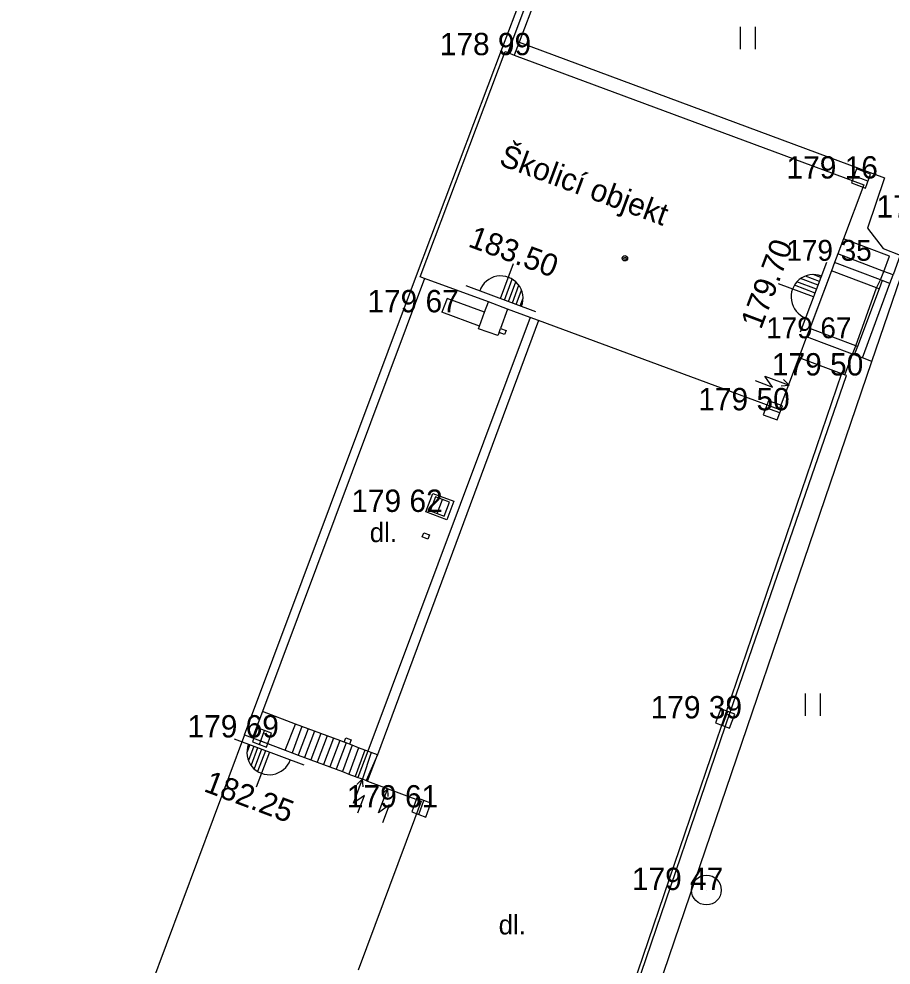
# Model space of a CAD drawing. Extents: x -537755 to -537431, y -1180722 to -1180510.
# Drawn here: x -537534.25 to -537504.97, y -1180583.92 to -1180552.16 of the extents above; entities that cross this region are included whole.
import ezdxf

# ---------------------------------------------------------------- set-up
doc = ezdxf.new("R2010")
doc.units = 0
for name, color, linetype in [('Vrstva 1', 7, 'Continuous'), ('Vrstva 11', 7, 'Continuous'), ('Vrstva 24', 7, 'Continuous'), ('Vrstva 27', 7, 'Continuous'), ('Vrstva 3', 7, 'Continuous'), ('Vrstva 36', 7, 'Continuous'), ('Vrstva 37', 7, 'Continuous'), ('Vrstva 39', 7, 'Continuous'), ('Vrstva 40', 7, 'Continuous'), ('Vrstva 41', 7, 'Continuous'), ('Vrstva 5', 7, 'Continuous'), ('Vrstva 6', 7, 'Continuous'), ('Vrstva 7', 7, 'Continuous')]:
    doc.layers.add(name, color=color, linetype=linetype)

msp = doc.modelspace()

# ---------------------------------------------------------------- linework, layer by layer
at = {"layer": 'Vrstva 1'}
for p, q in [((-537518.01, -1180553.12), (-537518.01, -1180553.12)), ((-537517.92, -1180553.26), (-537517.92, -1180553.26)), ((-537517.62, -1180553.38), (-537517.62, -1180553.38)), ((-537505.98, -1180557.52), (-537505.98, -1180557.52)), ((-537505.19, -1180557.5), (-537505.19, -1180557.5)), ((-537505.88, -1180557.73), (-537505.88, -1180557.73)), ((-537505.76, -1180559.19), (-537505.76, -1180559.19)), ((-537505.24, -1180559.87), (-537505.24, -1180559.87)), ((-537506.15, -1180560.28), (-537506.15, -1180560.28)), ((-537505.02, -1180560.13), (-537505.02, -1180560.13)), ((-537507.05, -1180560.83), (-537507.05, -1180560.83)), ((-537505.46, -1180561.19), (-537505.46, -1180561.19)), ((-537505.03, -1180561.09), (-537505.03, -1180561.09)), ((-537520.05, -1180562.01), (-537520.05, -1180562.01)), ((-537518.82, -1180562.56), (-537518.82, -1180562.56)), ((-537517.89, -1180562.62), (-537517.89, -1180562.62)), ((-537507.62, -1180562.34), (-537507.62, -1180562.34)), ((-537518.17, -1180562.79), (-537518.17, -1180562.79)), ((-537517.35, -1180562.88), (-537517.35, -1180562.88)), ((-537516.97, -1180562.72), (-537516.97, -1180562.72)), ((-537506.83, -1180562.88), (-537506.83, -1180562.88)), ((-537505.93, -1180563.54), (-537505.93, -1180563.54)), ((-537506.47, -1180564.13), (-537506.47, -1180564.13)), ((-537506.18, -1180564.21), (-537506.18, -1180564.21)), ((-537508.39, -1180564.46), (-537508.39, -1180564.46)), ((-537508.94, -1180565.3), (-537508.94, -1180565.3)), ((-537508.73, -1180565.27), (-537508.73, -1180565.27)), ((-537506.54, -1180566.1), (-537506.54, -1180566.1)), ((-537519.65, -1180568.35), (-537519.65, -1180568.35)), ((-537520.59, -1180568.71), (-537520.59, -1180568.71)), ((-537520.47, -1180569.48), (-537520.47, -1180569.48)), ((-537510.54, -1180575.64), (-537510.54, -1180575.64)), ((-537524.96, -1180575.83), (-537524.96, -1180575.83)), ((-537526.09, -1180576.28), (-537526.09, -1180576.28)), ((-537526.2, -1180576.37), (-537526.2, -1180576.37)), ((-537523.09, -1180576.36), (-537523.09, -1180576.36)), ((-537522.38, -1180576.32), (-537522.38, -1180576.32)), ((-537525.31, -1180576.71), (-537525.31, -1180576.71)), ((-537522.21, -1180576.86), (-537522.21, -1180576.86)), ((-537522.71, -1180577.67), (-537522.71, -1180577.67)), ((-537521.87, -1180577.99), (-537521.87, -1180577.99)), ((-537520.75, -1180578.42), (-537520.75, -1180578.42)), ((-537520.74, -1180578.63), (-537520.74, -1180578.63)), ((-537520.97, -1180579.02), (-537520.97, -1180579.02)), ((-537511.17, -1180581.4), (-537511.17, -1180581.4)), ((-537522.02, -1180581.84), (-537522.02, -1180581.84))]:
    msp.add_line(p, q, dxfattribs=at)
at = {"layer": 'Vrstva 11'}
for p, q in [((-537517.457, -1180552.946), (-537505.19, -1180557.5)), ((-537519.877, -1180561.541), (-537520.05, -1180562.01)), ((-537518.616, -1180562.007), (-537519.877, -1180561.541)), ((-537517.842, -1180561.902), (-537518.077, -1180562.55)), ((-537517.088, -1180562.181), (-537522.537, -1180576.738)), ((-537518.789, -1180562.476), (-537520.05, -1180562.01)), ((-537506.635, -1180564.068), (-537510.498, -1180575.39)), ((-537510.376, -1180575.435), (-537506.47, -1180564.13)), ((-537506.47, -1180564.13), (-537506.524, -1180564.11)), ((-537524.96, -1180575.83), (-537526.076, -1180575.412)), ((-537510.498, -1180575.39), (-537515.67, -1180590.55)), ((-537515.547, -1180590.592), (-537510.376, -1180575.435)), ((-537525.31, -1180576.71), (-537524.96, -1180575.83)), ((-537524.75, -1180575.909), (-537525.081, -1180576.791)), ((-537524.538, -1180575.988), (-537524.87, -1180576.87)), ((-537524.326, -1180576.067), (-537524.658, -1180576.95)), ((-537524.115, -1180576.147), (-537524.447, -1180577.029)), ((-537523.903, -1180576.226), (-537524.235, -1180577.109)), ((-537523.334, -1180576.439), (-537523.277, -1180576.29)), ((-537523.277, -1180576.29), (-537523.09, -1180576.36)), ((-537523.691, -1180576.305), (-537524.024, -1180577.189)), ((-537523.48, -1180576.384), (-537523.812, -1180577.268)), ((-537523.268, -1180576.464), (-537523.601, -1180577.348)), ((-537523.057, -1180576.543), (-537523.389, -1180577.427)), ((-537523.09, -1180576.36), (-537523.147, -1180576.509)), ((-537522.845, -1180576.622), (-537523.178, -1180577.507)), ((-537522.633, -1180576.701), (-537522.966, -1180577.586)), ((-537522.537, -1180576.738), (-537522.868, -1180577.623)), ((-537522.422, -1180576.781), (-537522.71, -1180577.67))]:
    msp.add_line(p, q, dxfattribs=at)
for points in [[(-537505.19, -1180557.5), (-537505.76, -1180559.19), (-537505.24, -1180559.87), (-537504.66, -1180560.09), (-537504.902, -1180560.752)], [(-537505.93, -1180563.54), (-537505.011, -1180561.039), (-537504.902, -1180560.752), (-537505.211, -1180560.635), (-537506.757, -1180560.051)], [(-537505.011, -1180561.039), (-537505.265, -1180560.943), (-537505.319, -1180560.922), (-537506.866, -1180560.338)], [(-537505.371, -1180561.223), (-537505.46, -1180561.19), (-537506.972, -1180560.619)], [(-537505.265, -1180560.943), (-537505.371, -1180561.223), (-537506.102, -1180563.155), (-537506.208, -1180563.436)], [(-537518.13, -1180562.69), (-537518.17, -1180562.79), (-537518.82, -1180562.56), (-537518.789, -1180562.476), (-537518.616, -1180562.007), (-537518.488, -1180561.663)], [(-537506.102, -1180563.155), (-537506.156, -1180563.135), (-537507.702, -1180562.55)], [(-537505.614, -1180563.66), (-537505.93, -1180563.54), (-537506.208, -1180563.436), (-537506.262, -1180563.416), (-537507.808, -1180562.831)], [(-537520.356, -1180568.086), (-537519.65, -1180568.35), (-537519.884, -1180568.974), (-537520.59, -1180568.71), (-537520.356, -1180568.086)], [(-537522.543, -1180577.746), (-537522.21, -1180576.86), (-537522.422, -1180576.781), (-537522.537, -1180576.738), (-537522.633, -1180576.701), (-537522.845, -1180576.622), (-537523.057, -1180576.543), (-537523.147, -1180576.509), (-537523.268, -1180576.464), (-537523.334, -1180576.439), (-537523.48, -1180576.384), (-537523.691, -1180576.305), (-537523.903, -1180576.226), (-537524.115, -1180576.147), (-537524.326, -1180576.067), (-537524.538, -1180575.988), (-537524.75, -1180575.909), (-537524.96, -1180575.83)]]:
    msp.add_lwpolyline(points, dxfattribs=at)
at = {"layer": 'Vrstva 24'}
for p, q in [((-537508.945, -1180564.518), (-537509.209, -1180564.151)), ((-537509.209, -1180564.151), (-537508.39, -1180564.46)), ((-537509.532, -1180564.296), (-537508.945, -1180564.518)), ((-537508.658, -1180564.475), (-537508.39, -1180564.46)), ((-537508.39, -1180564.46), (-537508.58, -1180564.27)), ((-537523.018, -1180578.489), (-537522.71, -1180577.67)), ((-537522.71, -1180577.67), (-537522.9, -1180577.86)), ((-537522.694, -1180577.938), (-537522.71, -1180577.67)), ((-537522.178, -1180578.809), (-537521.87, -1180577.99)), ((-537521.87, -1180577.99), (-537522.06, -1180578.18)), ((-537521.854, -1180578.258), (-537521.87, -1180577.99)), ((-537522.652, -1180578.225), (-537523.018, -1180578.489)), ((-537522.872, -1180578.812), (-537522.652, -1180578.225)), ((-537521.812, -1180578.545), (-537522.178, -1180578.809)), ((-537522.032, -1180579.132), (-537521.812, -1180578.545))]:
    msp.add_line(p, q, dxfattribs=at)
at = {"layer": 'Vrstva 27'}
for p, q in [((-537505.746, -1180557.607), (-537506.214, -1180557.433)), ((-537508.706, -1180565.387), (-537509.174, -1180565.213)), ((-537520.207, -1180568.764), (-537520.033, -1180568.296)), ((-537510.627, -1180575.874), (-537510.453, -1180575.406)), ((-537526.177, -1180576.514), (-537526.003, -1180576.046)), ((-537520.827, -1180578.864), (-537520.653, -1180578.396))]:
    msp.add_line(p, q, dxfattribs=at)
for points in [[(-537505.658, -1180557.373), (-537506.127, -1180557.198), (-537506.302, -1180557.667), (-537505.833, -1180557.842)], [(-537508.618, -1180565.153), (-537509.087, -1180564.978), (-537509.262, -1180565.447), (-537508.793, -1180565.622)], [(-537519.973, -1180568.852), (-537519.798, -1180568.383), (-537520.267, -1180568.208), (-537520.442, -1180568.677)], [(-537510.393, -1180575.962), (-537510.218, -1180575.493), (-537510.687, -1180575.318), (-537510.862, -1180575.787)], [(-537525.943, -1180576.602), (-537525.768, -1180576.133), (-537526.237, -1180575.958), (-537526.412, -1180576.427)], [(-537520.593, -1180578.952), (-537520.418, -1180578.483), (-537520.887, -1180578.308), (-537521.062, -1180578.777)]]:
    msp.add_lwpolyline(points, close=True, dxfattribs=at)
msp.add_circle((-537511.17, -1180581.4), 0.5, dxfattribs=at)
at = {"layer": 'Vrstva 36'}
for p, q in [((-537510.022, -1180553.183), (-537510.022, -1180552.433)), ((-537509.522, -1180553.183), (-537509.522, -1180552.433)), ((-537507.84, -1180575.551), (-537507.84, -1180574.801)), ((-537507.34, -1180575.551), (-537507.34, -1180574.801))]:
    msp.add_line(p, q, dxfattribs=at)
at = {"layer": 'Vrstva 37'}
for p, q in [((-537518.078, -1180561.548), (-537517.64, -1180560.369)), ((-537508.012, -1180562.665), (-537507.128, -1180560.327)), ((-537517.947, -1180561.597), (-537517.687, -1180560.898)), ((-537517.816, -1180561.646), (-537517.57, -1180560.986)), ((-537507.471, -1180561.234), (-537508.129, -1180560.985)), ((-537507.421, -1180561.103), (-537508.011, -1180560.88)), ((-537507.372, -1180560.972), (-537507.846, -1180560.793)), ((-537507.322, -1180560.841), (-537507.582, -1180560.743)), ((-537519.25, -1180561.113), (-537516.906, -1180561.983)), ((-537517.684, -1180561.694), (-537517.465, -1180561.104)), ((-537517.553, -1180561.743), (-537517.376, -1180561.268)), ((-537507.57, -1180561.496), (-537508.747, -1180561.051)), ((-537507.52, -1180561.365), (-537508.217, -1180561.102)), ((-537517.422, -1180561.792), (-537517.325, -1180561.531)), ((-537524.672, -1180577.213), (-537527.012, -1180576.331)), ((-537526.497, -1180576.525), (-537526.595, -1180576.785)), ((-537526.366, -1180576.575), (-537526.545, -1180577.049)), ((-537526.235, -1180576.624), (-537526.457, -1180577.214)), ((-537526.104, -1180576.673), (-537526.352, -1180577.332)), ((-537525.842, -1180576.772), (-537526.285, -1180577.949)), ((-537525.973, -1180576.723), (-537526.236, -1180577.42))]:
    msp.add_line(p, q, dxfattribs=at)
for centre, start, end in [((-537518.075, -1180561.54), 338.9961, 160.2421), ((-537507.578, -1180561.493), 68.663, 249.909), ((-537525.845, -1180576.78), 158.7366, 339.9827)]:
    msp.add_arc(centre, 0.75, start, end, dxfattribs=at)
at = {"layer": 'Vrstva 39'}
for radius in [0.09, 0.0398]:
    msp.add_circle((-537513.906, -1180560.195), radius, dxfattribs=at)
at = {"layer": 'Vrstva 5'}
for p, q in [((-537520.777, -1180560.817), (-537517.92, -1180553.26)), ((-537517.92, -1180553.26), (-537517.835, -1180553.292)), ((-537517.835, -1180553.292), (-537517.62, -1180553.38)), ((-537517.62, -1180553.38), (-537505.88, -1180557.73)), ((-537505.88, -1180557.73), (-537506.566, -1180559.546)), ((-537506.566, -1180559.546), (-537506.757, -1180560.051)), ((-537505.02, -1180560.13), (-537506.566, -1180559.546)), ((-537506.757, -1180560.051), (-537506.866, -1180560.338)), ((-537506.866, -1180560.338), (-537506.972, -1180560.619)), ((-537505.211, -1180560.635), (-537505.02, -1180560.13)), ((-537506.972, -1180560.619), (-537507.702, -1180562.55)), ((-537505.319, -1180560.922), (-537505.211, -1180560.635)), ((-537520.634, -1180560.87), (-537520.777, -1180560.817)), ((-537518.488, -1180561.663), (-537520.634, -1180560.87)), ((-537505.46, -1180561.19), (-537505.319, -1180560.922)), ((-537506.156, -1180563.135), (-537505.46, -1180561.19)), ((-537517.088, -1180562.181), (-537517.842, -1180561.902)), ((-537516.807, -1180562.285), (-537522.21, -1180576.86)), ((-537516.807, -1180562.285), (-537517.088, -1180562.181)), ((-537508.73, -1180565.27), (-537516.807, -1180562.285)), ((-537518.13, -1180562.69), (-537518.077, -1180562.55)), ((-537518.077, -1180562.55), (-537517.89, -1180562.62)), ((-537517.89, -1180562.62), (-537517.943, -1180562.76)), ((-537507.702, -1180562.55), (-537507.808, -1180562.831)), ((-537517.943, -1180562.76), (-537518.13, -1180562.69)), ((-537507.808, -1180562.831), (-537508.07, -1180563.525)), ((-537506.262, -1180563.416), (-537506.156, -1180563.135)), ((-537508.07, -1180563.525), (-537508.73, -1180565.27)), ((-537508.07, -1180563.525), (-537506.635, -1180564.068)), ((-537506.524, -1180564.11), (-537506.262, -1180563.416)), ((-537506.635, -1180564.068), (-537506.524, -1180564.11)), ((-537520.71, -1180569.55), (-537520.657, -1180569.41)), ((-537520.523, -1180569.62), (-537520.71, -1180569.55)), ((-537520.657, -1180569.41), (-537520.47, -1180569.48)), ((-537520.47, -1180569.48), (-537520.523, -1180569.62)), ((-537526.673, -1180576.192), (-537534.25, -1180596.49)), ((-537526.673, -1180576.192), (-537526.406, -1180576.293)), ((-537526.406, -1180576.293), (-537525.31, -1180576.71)), ((-537525.31, -1180576.71), (-537525.081, -1180576.791)), ((-537525.081, -1180576.791), (-537524.87, -1180576.87)), ((-537524.87, -1180576.87), (-537524.658, -1180576.95)), ((-537522.21, -1180576.86), (-537522.587, -1180577.729)), ((-537524.658, -1180576.95), (-537524.447, -1180577.029)), ((-537524.447, -1180577.029), (-537524.235, -1180577.109)), ((-537524.235, -1180577.109), (-537524.024, -1180577.189)), ((-537524.024, -1180577.189), (-537523.812, -1180577.268)), ((-537523.812, -1180577.268), (-537523.601, -1180577.348)), ((-537523.601, -1180577.348), (-537523.389, -1180577.427)), ((-537523.389, -1180577.427), (-537523.178, -1180577.507)), ((-537523.178, -1180577.507), (-537522.966, -1180577.586)), ((-537522.966, -1180577.586), (-537522.868, -1180577.623)), ((-537522.868, -1180577.623), (-537522.71, -1180577.67)), ((-537522.71, -1180577.67), (-537522.587, -1180577.729)), ((-537522.587, -1180577.729), (-537522.543, -1180577.746)), ((-537522.543, -1180577.746), (-537520.75, -1180578.42)), ((-537520.75, -1180578.42), (-537520.97, -1180579.02)), ((-537521.813, -1180581.267), (-537522.02, -1180581.84))]:
    msp.add_line(p, q, dxfattribs=at)
at = {"layer": 'Vrstva 6'}
for p, q in [((-537507.05, -1180560.83), (-537507.62, -1180562.34)), ((-537517.842, -1180561.902), (-537518.488, -1180561.663)), ((-537526.2, -1180576.37), (-537525.31, -1180576.71)), ((-537520.97, -1180579.02), (-537521.813, -1180581.267)), ((-537522.02, -1180581.84), (-537522.865, -1180584.086))]:
    msp.add_line(p, q, dxfattribs=at)
at = {"layer": 'Vrstva 7'}
for p, q in [((-537518.01, -1180553.12), (-537515.69, -1180546.957)), ((-537515.381, -1180546.773), (-537517.835, -1180553.292)), ((-537515.2, -1180546.95), (-537517.457, -1180552.946)), ((-537505.614, -1180563.66), (-537501.7, -1180552.176)), ((-537517.457, -1180552.946), (-537517.62, -1180553.38)), ((-537520.902, -1180560.771), (-537518.01, -1180553.12)), ((-537526.673, -1180576.192), (-537520.902, -1180560.771)), ((-537520.634, -1180560.87), (-537526.076, -1180575.412)), ((-537514.8, -1180590.62), (-537505.614, -1180563.66)), ((-537526.076, -1180575.412), (-537526.406, -1180576.293))]:
    msp.add_line(p, q, dxfattribs=at)

# ---------------------------------------------------------------- texts
at = {"layer": 'Vrstva 3'}
for s, height, p in [('178 99 ', 0.75, (-537520.12, -1180553.38)), ('179 16 ', 0.75, (-537508.48, -1180557.52)), ('179 31 ', 0.75, (-537505.46, -1180558.83)), ('179 35 ', 0.7, (-537508.483, -1180560.28)), ('179 67 ', 0.75, (-537522.55, -1180562.01)), ('179 67 ', 0.7, (-537509.163, -1180562.88)), ('179 50 ', 0.75, (-537508.97, -1180564.13)), ('179 50 ', 0.75, (-537511.44, -1180565.3)), ('179 62 ', 0.75, (-537523.09, -1180568.71)), ('179 39 ', 0.75, (-537513.04, -1180575.64)), ('179 69 ', 0.75, (-537528.59, -1180576.28)), ('179 61 ', 0.75, (-537523.24, -1180578.63)), ('179 47 ', 0.75, (-537513.67, -1180581.4))]:
    msp.add_text(s, height=height, dxfattribs=at).set_placement(p)
at = {"layer": 'Vrstva 37'}
for s, rotation, p in [('183.50', 339.7148, (-537519.204, -1180559.791)), ('179.70', 69.2942, (-537509.338, -1180562.613)), ('182.25', 339.3864, (-537528.079, -1180578.074))]:
    msp.add_text(s, height=0.75, rotation=rotation, dxfattribs=at).set_placement(p)
at = {"layer": 'Vrstva 40'}
for p in [(-537522.472, -1180569.723), (-537518.144, -1180582.89)]:
    msp.add_text('dl.', height=0.65, dxfattribs=at).set_placement(p)
at = {"layer": 'Vrstva 41'}
msp.add_text('Školicí objekt', height=0.75, rotation=339.6319, dxfattribs=at).set_placement((-537518.167, -1180557.055))

doc.saveas('drawing.dxf')
